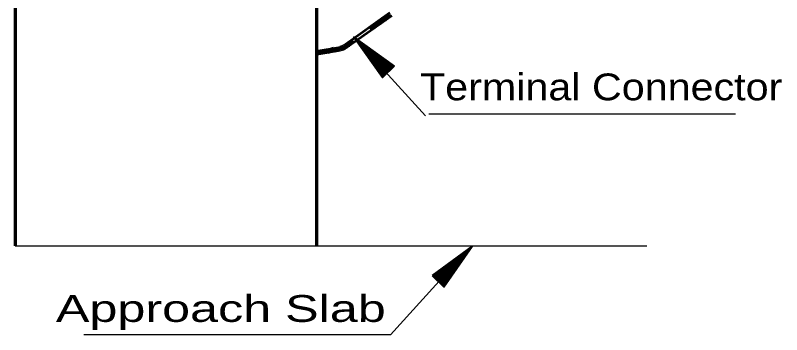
# Model space of a CAD drawing. Extents: x 856.9 to 891.7, y -2278.5 to -2254.7.
# Drawn here: x 864.157 to 867.829, y -2262.231 to -2260.699 of the extents above; entities that cross this region are included whole.
import ezdxf

# ---------------------------------------------------------------- set-up
doc = ezdxf.new("R2010")
doc.units = 0
doc.header["$LTSCALE"] = 0.051
doc.layers.add('1', color=7, linetype='Continuous', lineweight=70)
doc.layers.add('3', color=7, linetype='Continuous', lineweight=40)

msp = doc.modelspace()

# ---------------------------------------------------------------- hatches: boundary and pattern name
at = {"layer": '3'}
for points in [[(865.972, -2260.94242), (865.91642, -2260.99725), (865.77967, -2260.80325), (865.77967, -2260.80325)], [(865.96842, -2260.94433), (865.9185, -2260.99375), (865.79533, -2260.81925), (865.79533, -2260.81925)], [(865.96517, -2260.94617), (865.92033, -2260.99058), (865.8095, -2260.8335), (865.8095, -2260.8335)], [(865.96242, -2260.94775), (865.92208, -2260.98767), (865.82225, -2260.84633), (865.82225, -2260.84633)], [(865.96, -2260.94925), (865.9235, -2260.98508), (865.83375, -2260.85792), (865.83375, -2260.85792)], [(865.9575, -2260.95042), (865.92475, -2260.98283), (865.844, -2260.86833), (865.844, -2260.86833)], [(865.95542, -2260.95175), (865.926, -2260.98092), (865.85325, -2260.87775), (865.85325, -2260.87775)], [(865.9535, -2260.95258), (865.92717, -2260.979), (865.86175, -2260.88625), (865.86175, -2260.88625)], [(865.95208, -2260.95367), (865.92792, -2260.97725), (865.86917, -2260.89383), (865.86917, -2260.89383)], [(865.95042, -2260.9545), (865.92867, -2260.97583), (865.87592, -2260.90067), (865.87592, -2260.90067)], [(865.949, -2260.95525), (865.92967, -2260.97433), (865.882, -2260.90692), (865.882, -2260.90692)], [(865.94775, -2260.95608), (865.93042, -2260.97317), (865.88742, -2260.9125), (865.88742, -2260.9125)], [(865.94667, -2260.95658), (865.931, -2260.97208), (865.8925, -2260.9175), (865.8925, -2260.9175)], [(865.94558, -2260.95708), (865.93158, -2260.97117), (865.89683, -2260.92175), (865.89683, -2260.92175)], [(865.94475, -2260.95758), (865.93208, -2260.97025), (865.90092, -2260.92583), (865.90092, -2260.92583)], [(865.944, -2260.95808), (865.9325, -2260.9695), (865.90433, -2260.92958), (865.90433, -2260.92958)], [(865.94317, -2260.95858), (865.93283, -2260.96883), (865.90758, -2260.93283), (865.90758, -2260.93283)], [(865.94258, -2260.959), (865.93333, -2260.96808), (865.91042, -2260.93575), (865.91042, -2260.93575)], [(865.942, -2260.959), (865.93375, -2260.9675), (865.91317, -2260.93825), (865.91317, -2260.93825)], [(865.9415, -2260.95933), (865.934, -2260.96683), (865.91542, -2260.9405), (865.91542, -2260.9405)], [(865.94108, -2260.95933), (865.93425, -2260.96608), (865.91775, -2260.9425), (865.91775, -2260.9425)], [(865.94067, -2260.95983), (865.93458, -2260.96575), (865.91967, -2260.9445), (865.91967, -2260.9445)], [(865.94025, -2260.96), (865.93475, -2260.96533), (865.92117, -2260.94633), (865.92117, -2260.94633)], [(865.93992, -2260.96017), (865.935, -2260.965), (865.92283, -2260.94775), (865.92283, -2260.94775)], [(866.15433, -2261.94608), (866.20992, -2262.00092), (866.34667, -2261.80692), (866.34667, -2261.80692)], [(866.15792, -2261.948), (866.20783, -2261.99742), (866.331, -2261.82292), (866.331, -2261.82292)], [(866.16117, -2261.94983), (866.206, -2261.99425), (866.31683, -2261.83717), (866.31683, -2261.83717)], [(866.16392, -2261.95142), (866.20425, -2261.99133), (866.30408, -2261.85), (866.30408, -2261.85)], [(866.16633, -2261.95292), (866.20283, -2261.98875), (866.29258, -2261.86158), (866.29258, -2261.86158)], [(866.16883, -2261.95408), (866.20158, -2261.9865), (866.28233, -2261.872), (866.28233, -2261.872)], [(866.17092, -2261.95542), (866.20033, -2261.98458), (866.27308, -2261.88142), (866.27308, -2261.88142)], [(866.17283, -2261.95625), (866.19917, -2261.98267), (866.26458, -2261.88992), (866.26458, -2261.88992)], [(866.17425, -2261.95733), (866.19842, -2261.98092), (866.25717, -2261.8975), (866.25717, -2261.8975)], [(866.17592, -2261.95817), (866.19767, -2261.9795), (866.25042, -2261.90433), (866.25042, -2261.90433)], [(866.17733, -2261.95892), (866.19667, -2261.978), (866.24433, -2261.91058), (866.24433, -2261.91058)], [(866.17858, -2261.95975), (866.19592, -2261.97683), (866.23892, -2261.91617), (866.23892, -2261.91617)], [(866.17967, -2261.96025), (866.19533, -2261.97575), (866.23383, -2261.92117), (866.23383, -2261.92117)], [(866.18075, -2261.96075), (866.19475, -2261.97483), (866.2295, -2261.92542), (866.2295, -2261.92542)], [(866.18158, -2261.96125), (866.19425, -2261.97392), (866.22542, -2261.9295), (866.22542, -2261.9295)], [(866.18233, -2261.96175), (866.19383, -2261.97317), (866.222, -2261.93325), (866.222, -2261.93325)], [(866.18317, -2261.96225), (866.1935, -2261.9725), (866.21875, -2261.9365), (866.21875, -2261.9365)], [(866.18375, -2261.96267), (866.193, -2261.97175), (866.21592, -2261.93942), (866.21592, -2261.93942)], [(866.18433, -2261.96267), (866.19258, -2261.97117), (866.21317, -2261.94192), (866.21317, -2261.94192)], [(866.18483, -2261.963), (866.19233, -2261.9705), (866.21092, -2261.94417), (866.21092, -2261.94417)], [(866.18525, -2261.963), (866.19208, -2261.96975), (866.20858, -2261.94617), (866.20858, -2261.94617)], [(866.18567, -2261.9635), (866.19175, -2261.96942), (866.20667, -2261.94817), (866.20667, -2261.94817)], [(866.18608, -2261.96367), (866.19158, -2261.969), (866.20517, -2261.95), (866.20517, -2261.95)], [(866.18642, -2261.96383), (866.19133, -2261.96867), (866.2035, -2261.95142), (866.2035, -2261.95142)]]:
    msp.add_hatch(color=256, dxfattribs=at).paths.add_polyline_path(points)

# ---------------------------------------------------------------- linework, layer by layer
at = {"layer": '1'}
for p, q in [((864.15717, -2258.33842), (864.15717, -2261.80517)), ((865.59983, -2259.76317), (865.59983, -2261.80517)), ((865.91542, -2260.71367), (865.95792, -2260.7005)), ((865.86492, -2260.75067), (865.90792, -2260.73575)), ((865.88992, -2260.7315), (865.93283, -2260.71817)), ((865.85767, -2260.75525), (865.86492, -2260.76542)), ((865.86217, -2260.76117), (865.88258, -2260.754)), ((865.65608, -2260.87567), (865.75883, -2260.84192)), ((865.73958, -2260.83892), (865.77367, -2260.829)), ((865.75283, -2260.82992), (865.77083, -2260.82425)), ((865.76783, -2260.82), (865.77517, -2260.82992)), ((865.60167, -2260.883), (865.68383, -2260.85675)), ((865.68833, -2260.86992), (865.74558, -2260.85075))]:
    msp.add_line(p, q, dxfattribs=at)
at = {"layer": '1', "lineweight": 53}
for p, q in [((865.95233, -2260.68767), (865.73258, -2260.844)), ((865.74108, -2260.855), (865.96092, -2260.699)), ((865.71517, -2260.85267), (865.59833, -2260.87175)), ((865.60167, -2260.88467), (865.71608, -2260.8655))]:
    msp.add_line(p, q, dxfattribs=at)
at = {"layer": '1', "lineweight": 13}
for p, q in [((865.62342, -2260.88167), (865.77083, -2260.83317)), ((865.59983, -2260.88017), (865.65117, -2260.86242)), ((865.59983, -2260.87142), (865.60167, -2260.88467))]:
    msp.add_line(p, q, dxfattribs=at)
at = {"layer": '1', "lineweight": 25}
for p, q in [((865.81233, -2260.84025), (866.12192, -2261.18108)), ((867.60867, -2261.17258), (866.13892, -2261.17258)), ((864.15717, -2261.80517), (867.18392, -2261.80517))]:
    msp.add_line(p, q, dxfattribs=at)
msp.add_lwpolyline([(866.26442, -2261.88992), (865.95483, -2262.23075), (864.48508, -2262.23075)], dxfattribs=at)
at = {"layer": '1'}
msp.add_arc((865.70639, -2260.80632), 0.04603, 280.00158, 305.49118, dxfattribs=at)
at = {"layer": '1', "lineweight": 53}
msp.add_arc((865.70639, -2260.80632), 0.05966, 280.00158, 305.49118, dxfattribs=at)
at = {"layer": '3'}
for points in [[(865.972, -2260.94242), (865.91642, -2260.99725), (865.77967, -2260.80325), (865.77967, -2260.80325)], [(865.96842, -2260.94433), (865.9185, -2260.99375), (865.79533, -2260.81925), (865.79533, -2260.81925)], [(865.96517, -2260.94617), (865.92033, -2260.99058), (865.8095, -2260.8335), (865.8095, -2260.8335)], [(865.96242, -2260.94775), (865.92208, -2260.98767), (865.82225, -2260.84633), (865.82225, -2260.84633)], [(865.96, -2260.94925), (865.9235, -2260.98508), (865.83375, -2260.85792), (865.83375, -2260.85792)], [(865.9575, -2260.95042), (865.92475, -2260.98283), (865.844, -2260.86833), (865.844, -2260.86833)], [(865.95542, -2260.95175), (865.926, -2260.98092), (865.85325, -2260.87775), (865.85325, -2260.87775)], [(865.9535, -2260.95258), (865.92717, -2260.979), (865.86175, -2260.88625), (865.86175, -2260.88625)], [(865.95208, -2260.95367), (865.92792, -2260.97725), (865.86917, -2260.89383), (865.86917, -2260.89383)], [(865.95042, -2260.9545), (865.92867, -2260.97583), (865.87592, -2260.90067), (865.87592, -2260.90067)], [(865.949, -2260.95525), (865.92967, -2260.97433), (865.882, -2260.90692), (865.882, -2260.90692)], [(865.94775, -2260.95608), (865.93042, -2260.97317), (865.88742, -2260.9125), (865.88742, -2260.9125)], [(865.94667, -2260.95658), (865.931, -2260.97208), (865.8925, -2260.9175), (865.8925, -2260.9175)], [(865.94558, -2260.95708), (865.93158, -2260.97117), (865.89683, -2260.92175), (865.89683, -2260.92175)], [(865.94475, -2260.95758), (865.93208, -2260.97025), (865.90092, -2260.92583), (865.90092, -2260.92583)], [(865.944, -2260.95808), (865.9325, -2260.9695), (865.90433, -2260.92958), (865.90433, -2260.92958)], [(865.94317, -2260.95858), (865.93283, -2260.96883), (865.90758, -2260.93283), (865.90758, -2260.93283)], [(865.94258, -2260.959), (865.93333, -2260.96808), (865.91042, -2260.93575), (865.91042, -2260.93575)], [(865.942, -2260.959), (865.93375, -2260.9675), (865.91317, -2260.93825), (865.91317, -2260.93825)], [(865.9415, -2260.95933), (865.934, -2260.96683), (865.91542, -2260.9405), (865.91542, -2260.9405)], [(865.94108, -2260.95933), (865.93425, -2260.96608), (865.91775, -2260.9425), (865.91775, -2260.9425)], [(865.94067, -2260.95983), (865.93458, -2260.96575), (865.91967, -2260.9445), (865.91967, -2260.9445)], [(865.94025, -2260.96), (865.93475, -2260.96533), (865.92117, -2260.94633), (865.92117, -2260.94633)], [(865.93992, -2260.96017), (865.935, -2260.965), (865.92283, -2260.94775), (865.92283, -2260.94775)], [(866.15433, -2261.94608), (866.20992, -2262.00092), (866.34667, -2261.80692), (866.34667, -2261.80692)], [(866.15792, -2261.948), (866.20783, -2261.99742), (866.331, -2261.82292), (866.331, -2261.82292)], [(866.16117, -2261.94983), (866.206, -2261.99425), (866.31683, -2261.83717), (866.31683, -2261.83717)], [(866.16392, -2261.95142), (866.20425, -2261.99133), (866.30408, -2261.85), (866.30408, -2261.85)], [(866.16633, -2261.95292), (866.20283, -2261.98875), (866.29258, -2261.86158), (866.29258, -2261.86158)], [(866.16883, -2261.95408), (866.20158, -2261.9865), (866.28233, -2261.872), (866.28233, -2261.872)], [(866.17092, -2261.95542), (866.20033, -2261.98458), (866.27308, -2261.88142), (866.27308, -2261.88142)], [(866.17283, -2261.95625), (866.19917, -2261.98267), (866.26458, -2261.88992), (866.26458, -2261.88992)], [(866.17425, -2261.95733), (866.19842, -2261.98092), (866.25717, -2261.8975), (866.25717, -2261.8975)], [(866.17592, -2261.95817), (866.19767, -2261.9795), (866.25042, -2261.90433), (866.25042, -2261.90433)], [(866.17733, -2261.95892), (866.19667, -2261.978), (866.24433, -2261.91058), (866.24433, -2261.91058)], [(866.17858, -2261.95975), (866.19592, -2261.97683), (866.23892, -2261.91617), (866.23892, -2261.91617)], [(866.17967, -2261.96025), (866.19533, -2261.97575), (866.23383, -2261.92117), (866.23383, -2261.92117)], [(866.18075, -2261.96075), (866.19475, -2261.97483), (866.2295, -2261.92542), (866.2295, -2261.92542)], [(866.18158, -2261.96125), (866.19425, -2261.97392), (866.22542, -2261.9295), (866.22542, -2261.9295)], [(866.18233, -2261.96175), (866.19383, -2261.97317), (866.222, -2261.93325), (866.222, -2261.93325)], [(866.18317, -2261.96225), (866.1935, -2261.9725), (866.21875, -2261.9365), (866.21875, -2261.9365)], [(866.18375, -2261.96267), (866.193, -2261.97175), (866.21592, -2261.93942), (866.21592, -2261.93942)], [(866.18433, -2261.96267), (866.19258, -2261.97117), (866.21317, -2261.94192), (866.21317, -2261.94192)], [(866.18483, -2261.963), (866.19233, -2261.9705), (866.21092, -2261.94417), (866.21092, -2261.94417)], [(866.18525, -2261.963), (866.19208, -2261.96975), (866.20858, -2261.94617), (866.20858, -2261.94617)], [(866.18567, -2261.9635), (866.19175, -2261.96942), (866.20667, -2261.94817), (866.20667, -2261.94817)], [(866.18608, -2261.96367), (866.19158, -2261.969), (866.20517, -2261.95), (866.20517, -2261.95)], [(866.18642, -2261.96383), (866.19133, -2261.96867), (866.2035, -2261.95142), (866.2035, -2261.95142)]]:
    msp.add_lwpolyline(points, close=True, dxfattribs=at)

# ---------------------------------------------------------------- texts
at = {"layer": '1'}
for s, height, width, p in [('Terminal Connector', 0.1286, 1.15, (866.09608, -2261.1065)), ('Approach Slab', 0.1287, 1.4, (864.35158, -2262.1695))]:
    msp.add_text(s, height=height, dxfattribs=dict(at, width=width)).set_placement(p)

doc.saveas('drawing.dxf')
